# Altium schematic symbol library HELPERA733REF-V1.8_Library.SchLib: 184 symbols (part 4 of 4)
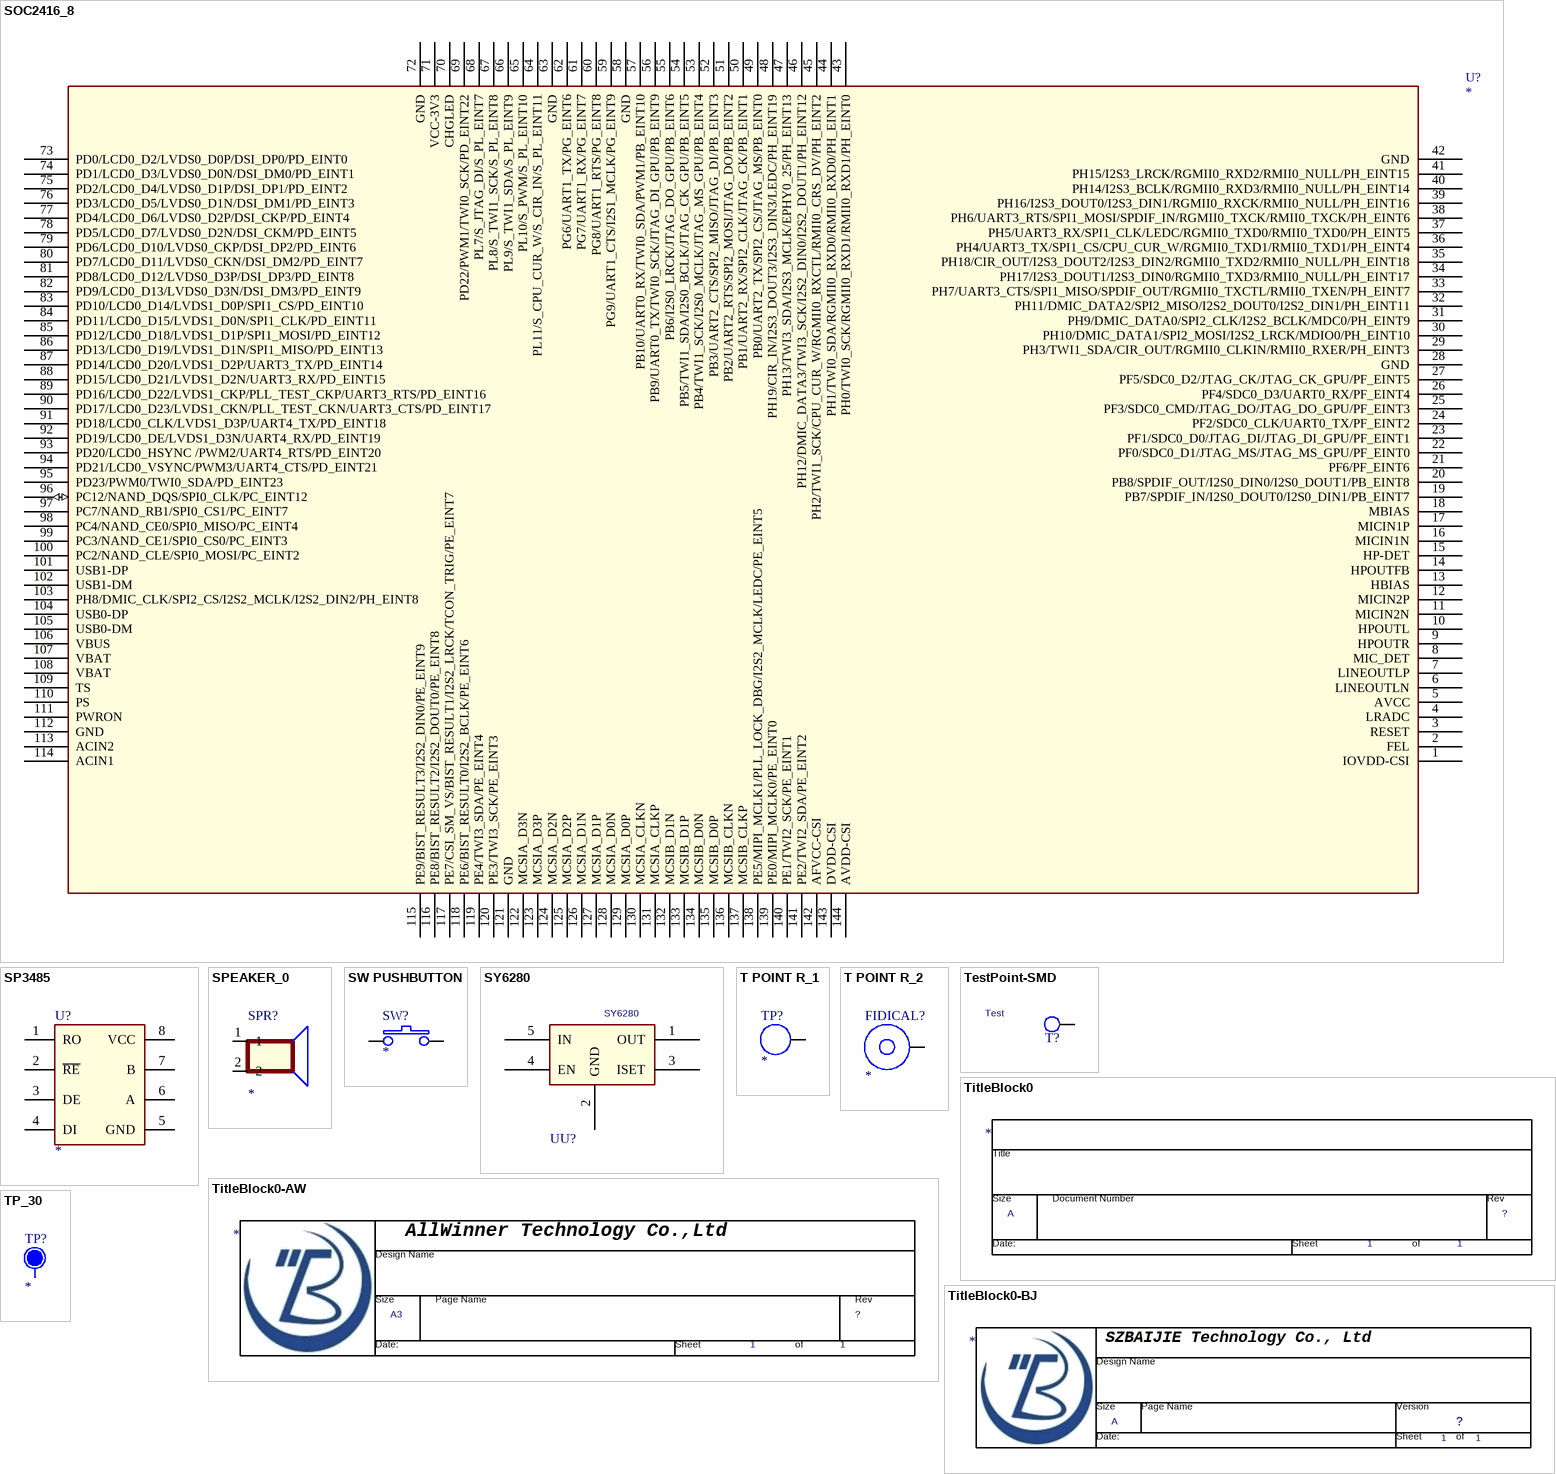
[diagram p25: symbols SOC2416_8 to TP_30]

## SOC2416_8
designator U?
footprint SOC4X4_1MM
pins: 1 IOVDD-CSI, 2 FEL, 3 RESET, 4 LRADC, 5 AVCC, 6 LINEOUTLN, 7 LINEOUTLP, 8 MIC_DET, 9 HPOUTR, 10 HPOUTL, 11 MICIN2N, 12 MICIN2P, 13 HBIAS, 14 HPOUTFB, 15 HP-DET, 16 MICIN1N, 17 MICIN1P, 18 MBIAS, 19 PB7/SPDIF_IN/I2S0_DOUT0/I2S0_DIN1/PB_EINT7, 20 PB8/SPDIF_OUT/I2S0_DIN0/I2S0_DOUT1/PB_EINT8, 21 PF6/PF_EINT6, 22 PF0/SDC0_D1/JTAG_MS/JTAG_MS_GPU/PF_EINT0, 23 PF1/SDC0_D0/JTAG_DI/JTAG_DI_GPU/PF_EINT1, 24 PF2/SDC0_CLK/UART0_TX/PF_EINT2, 25 PF3/SDC0_CMD/JTAG_DO/JTAG_DO_GPU/PF_EINT3, 26 PF4/SDC0_D3/UART0_RX/PF_EINT4, 27 PF5/SDC0_D2/JTAG_CK/JTAG_CK_GPU/PF_EINT5, 28 GND, 29 PH3/TWI1_SDA/CIR_OUT/RGMII0_CLKIN/RMII0_RXER/PH_EINT3, 30 PH10/DMIC_DATA1/SPI2_MOSI/I2S2_LRCK/MDIO0/PH_EINT10, 31 PH9/DMIC_DATA0/SPI2_CLK/I2S2_BCLK/MDC0/PH_EINT9, 32 PH11/DMIC_DATA2/SPI2_MISO/I2S2_DOUT0/I2S2_DIN1/PH_EINT11, 33 PH7/UART3_CTS/SPI1_MISO/SPDIF_OUT/RGMII0_TXCTL/RMII0_TXEN/PH_EINT7, 34 PH17/I2S3_DOUT1/I2S3_DIN0/RGMII0_TXD3/RMII0_NULL/PH_EINT17, 35 PH18/CIR_OUT/I2S3_DOUT2/I2S3_DIN2/RGMII0_TXD2/RMII0_NULL/PH_EINT18, 36 PH4/UART3_TX/SPI1_CS/CPU_CUR_W/RGMII0_TXD1/RMII0_TXD1/PH_EINT4, 37 PH5/UART3_RX/SPI1_CLK/LEDC/RGMII0_TXD0/RMII0_TXD0/PH_EINT5, 38 PH6/UART3_RTS/SPI1_MOSI/SPDIF_IN/RGMII0_TXCK/RMII0_TXCK/PH_EINT6, 39 PH16/I2S3_DOUT0/I2S3_DIN1/RGMII0_RXCK/RMII0_NULL/PH_EINT16, 40 PH14/I2S3_BCLK/RGMII0_RXD3/RMII0_NULL/PH_EINT14, 41 PH15/I2S3_LRCK/RGMII0_RXD2/RMII0_NULL/PH_EINT15, 42 GND, 43 PH0/TWI0_SCK/RGMII0_RXD1/RMII0_RXD1/PH_EINT0, 44 PH1/TWI0_SDA/RGMII0_RXD0/RMII0_RXD0/PH_EINT1, 45 PH2/TWI1_SCK/CPU_CUR_W/RGMII0_RXCTL/RMII0_CRS_DV/PH_EINT2, 46 PH12/DMIC_DATA3/TWI3_SCK/I2S2_DIN0/I2S2_DOUT1/PH_EINT12, 47 PH13/TWI3_SDA/I2S3_MCLK/EPHY0_25/PH_EINT13, 48 PH19/CIR_IN/I2S3_DOUT3/I2S3_DIN3/LEDC/PH_EINT19, 49 PB0/UART2_TX/SPI2_CS/JTAG_MS/PB_EINT0, 50 PB1/UART2_RX/SPI2_CLK/JTAG_CK/PB_EINT1, 51 PB2/UART2_RTS/SPI2_MOSI/JTAG_DO/PB_EINT2, 52 PB3/UART2_CTS/SPI2_MISO/JTAG_DI/PB_EINT3, 53 PB4/TWI1_SCK/I2S0_MCLK/JTAG_MS_GPU/PB_EINT4, 54 PB5/TWI1_SDA/I2S0_BCLK/JTAG_CK_GPU/PB_EINT5, 55 PB6/I2S0_LRCK/JTAG_DO_GPU/PB_EINT6, 56 PB9/UART0_TX/TWI0_SCK/JTAG_DI_GPU/PB_EINT9, 57 PB10/UART0_RX/TWI0_SDA/PWM1/PB_EINT10 (power), 58 GND, 59 PG9/UART1_CTS/I2S1_MCLK/PG_EINT9, 60 PG8/UART1_RTS/PG_EINT8, 61 PG7/UART1_RX/PG_EINT7, 62 PG6/UART1_TX/PG_EINT6, 63 GND, 64 PL11/S_CPU_CUR_W/S_CIR_IN/S_PL_EINT11, 65 PL10/S_PWM/S_PL_EINT10, 66 PL9/S_TWI1_SDA/S_PL_EINT9, 67 PL8/S_TWI1_SCK/S_PL_EINT8, 68 PL7/S_JTAG_DI/S_PL_EINT7, 69 PD22/PWM1/TWI0_SCK/PD_EINT22, 70 CHGLED, 71 VCC-3V3, 72 GND, 73 PD0/LCD0_D2/LVDS0_D0P/DSI_DP0/PD_EINT0, 74 PD1/LCD0_D3/LVDS0_D0N/DSI_DM0/PD_EINT1, 75 PD2/LCD0_D4/LVDS0_D1P/DSI_DP1/PD_EINT2, 76 PD3/LCD0_D5/LVDS0_D1N/DSI_DM1/PD_EINT3, 77 PD4/LCD0_D6/LVDS0_D2P/DSI_CKP/PD_EINT4, 78 PD5/LCD0_D7/LVDS0_D2N/DSI_CKM/PD_EINT5, 79 PD6/LCD0_D10/LVDS0_CKP/DSI_DP2/PD_EINT6, 80 PD7/LCD0_D11/LVDS0_CKN/DSI_DM2/PD_EINT7, 81 PD8/LCD0_D12/LVDS0_D3P/DSI_DP3/PD_EINT8, 82 PD9/LCD0_D13/LVDS0_D3N/DSI_DM3/PD_EINT9, 83 PD10/LCD0_D14/LVDS1_D0P/SPI1_CS/PD_EINT10, 84 PD11/LCD0_D15/LVDS1_D0N/SPI1_CLK/PD_EINT11, 85 PD12/LCD0_D18/LVDS1_D1P/SPI1_MOSI/PD_EINT12, 86 PD13/LCD0_D19/LVDS1_D1N/SPI1_MISO/PD_EINT13, 87 PD14/LCD0_D20/LVDS1_D2P/UART3_TX/PD_EINT14, 88 PD15/LCD0_D21/LVDS1_D2N/UART3_RX/PD_EINT15, 89 PD16/LCD0_D22/LVDS1_CKP/PLL_TEST_CKP/UART3_RTS/PD_EINT16, 90 PD17/LCD0_D23/LVDS1_CKN/PLL_TEST_CKN/UART3_CTS/PD_EINT17, 91 PD18/LCD0_CLK/LVDS1_D3P/UART4_TX/PD_EINT18, 92 PD19/LCD0_DE/LVDS1_D3N/UART4_RX/PD_EINT19, 93 PD20/LCD0_HSYNC /PWM2/UART4_RTS/PD_EINT20, 94 PD21/LCD0_VSYNC/PWM3/UART4_CTS/PD_EINT21, 95 PD23/PWM0/TWI0_SDA/PD_EINT23, 96 PC12/NAND_DQS/SPI0_CLK/PC_EINT12 (io), 97 PC7/NAND_RB1/SPI0_CS1/PC_EINT7, 98 PC4/NAND_CE0/SPI0_MISO/PC_EINT4, 99 PC3/NAND_CE1/SPI0_CS0/PC_EINT3, 100 PC2/NAND_CLE/SPI0_MOSI/PC_EINT2, 101 USB1-DP, 102 USB1-DM, 103 PH8/DMIC_CLK/SPI2_CS/I2S2_MCLK/I2S2_DIN2/PH_EINT8, 104 USB0-DP, 105 USB0-DM, 106 VBUS, 107 VBAT, 108 VBAT, 109 TS, 110 PS, 111 PWRON, 112 GND, 113 ACIN2, 114 ACIN1, 115 PE9/BIST_RESULT3/I2S2_DIN0/PE_EINT9, 116 PE8/BIST_RESULT2/I2S2_DOUT0/PE_EINT8, 117 PE7/CSI_SM_VS/BIST_RESULT1/I2S2_LRCK/TCON_TRIG/PE_EINT7, 118 PE6/BIST_RESULT0/I2S2_BCLK/PE_EINT6, 119 PE4/TWI3_SDA/PE_EINT4, 120 PE3/TWI3_SCK/PE_EINT3, 121 GND, 122 MCSIA_D3N, 123 MCSIA_D3P, 124 MCSIA_D2N, 125 MCSIA_D2P, 126 MCSIA_D1N, 127 MCSIA_D1P, 128 MCSIA_D0N, 129 MCSIA_D0P, 130 MCSIA_CLKN, 131 MCSIA_CLKP, 132 MCSIB_D1N, 133 MCSIB_D1P, 134 MCSIB_D0N, 135 MCSIB_D0P, 136 MCSIB_CLKN, 137 MCSIB_CLKP, 138 PE5/MIPI_MCLK1/PLL_LOCK_DBG/I2S2_MCLK/LEDC/PE_EINT5, 139 PE0/MIPI_MCLK0/PE_EINT0, 140 PE1/TWI2_SCK/PE_EINT1, 141 PE2/TWI2_SDA/PE_EINT2, 142 AFVCC-CSI, 143 DVDD-CSI, 144 AVDD-CSI

## SP3485
designator U?
footprint SO8
pins: 1 RO, 2 ~{RE}, 3 DE, 4 DI, 5 GND, 6 A, 7 B, 8 VCC

## SPEAKER_0
designator SPR?
footprint SPEAKER
pins: 1, 2

## SW PUSHBUTTON
designator SW?
pins: 1, 2

## SY6280
designator UU?
footprint SOP9P1_27B3_90X4_90H1_70
pins: 1 OUT, 2 GND, 3 ISET, 4 EN, 5 IN

## T POINT R_1
designator TP?
pins: 1 TP

## T POINT R_2
designator FIDICAL?
footprint FIDICALMARK
pins: 1 TP

## TestPoint-SMD
designator T?, comment Test
Parameter: 独立焊盘式测试点
footprint TP100
pins: 1 TP

## TitleBlock0
designator *  Page Size: A  Page Number: 1  (graphical)

## TitleBlock0-AW
designator *  Page Count: 1  Page Size: A3  (graphical)

## TitleBlock0-BJ
designator *  Page Count: 1  Page Size: A  (graphical)

## TP_30
designator TP?
Editor: Wenson
footprint TP_30
pins: 1

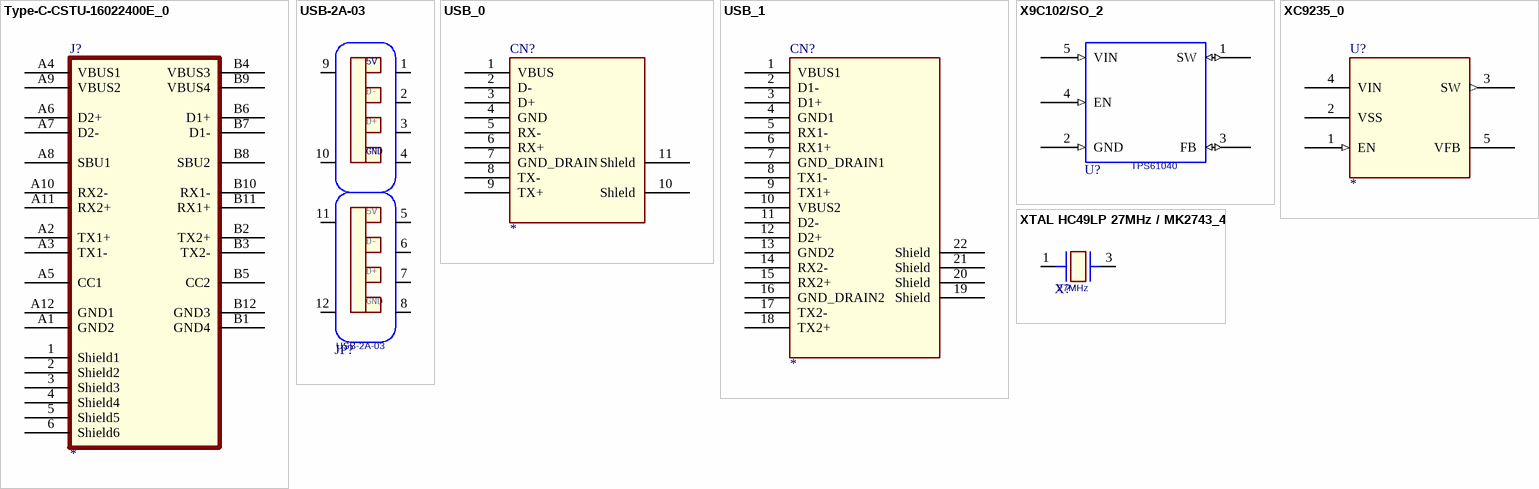
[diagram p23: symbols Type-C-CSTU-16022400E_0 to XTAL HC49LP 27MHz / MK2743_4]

## Type-C-CSTU-16022400E_0
designator J?
footprint USB28P50B790_894H316
pins: 1 Shield1, 2 Shield2, 3 Shield3, 4 Shield4, 5 Shield5, 6 Shield6, A1 GND2, A2 TX1+, A3 TX1-, A4 VBUS1, A5 CC1, A6 D2+, A7 D2-, A8 SBU1, A9 VBUS2, A10 RX2-, A11 RX2+, A12 GND1, B1 GND4, B2 TX2+, B3 TX2-, B4 VBUS3, B5 CC2, B6 D1+, B7 D1-, B8 SBU2, B9 VBUS4, B10 RX1-, B11 RX1+, B12 GND3

## USB-2A-03
designator JP?
footprint MINI-B
pins: 1 VBUS, 2 D-, 3 D+, 4 GND, 5 VBUS, 6 D-, 7 D+, 8 GND, 9 S1, 10 S2, 11 S3, 12 S4

## USB_0
designator CN?
footprint Series B
pins: 1 VBUS, 2 D-, 3 D+, 4 GND, 5 RX-, 6 RX+, 7 GND_DRAIN, 8 TX-, 9 TX+, 10 Shleld, 11 Shleld

## USB_1
designator CN?
footprint Series B
pins: 1 VBUS1, 2 D1-, 3 D1+, 4 GND1, 5 RX1-, 6 RX1+, 7 GND_DRAIN1, 8 TX1-, 9 TX1+, 10 VBUS2, 11 D2-, 12 D2+, 13 GND2, 14 RX2-, 15 RX2+, 16 GND_DRAIN2, 17 TX2-, 18 TX2+, 19 Shield, 20 Shield, 21 Shield, 22 Shield

## X9C102/SO_2
designator U?, comment TPS61040
pins: 1 SW (io), 2 GND (in), 3 FB (io), 4 EN (in), 5 VIN (in)

## XC9235_0
designator U?
pins: 1 EN (in), 2 VSS (power), 3 SW (out), 4 VIN (power), 5 VFB (power)

## XTAL HC49LP 27MHz / MK2743_4
designator X?, comment 27MHz
04 MPN: B18CA1-27.000MHZ; 30 VENDOR: MMD Components; 03 MAN: MMD; 21 FOOTPRINT: HC49 thr. hole d=4.88mm+/-0.2mm; 22 HEIGHT: 3.5mm; 01 IPN: 13-000162-01; 20 PACKAGE: HC49; 02 DESC: X-Tal 27.000 MHz 15/30ppm
footprint XTAL
pins: 1, 3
